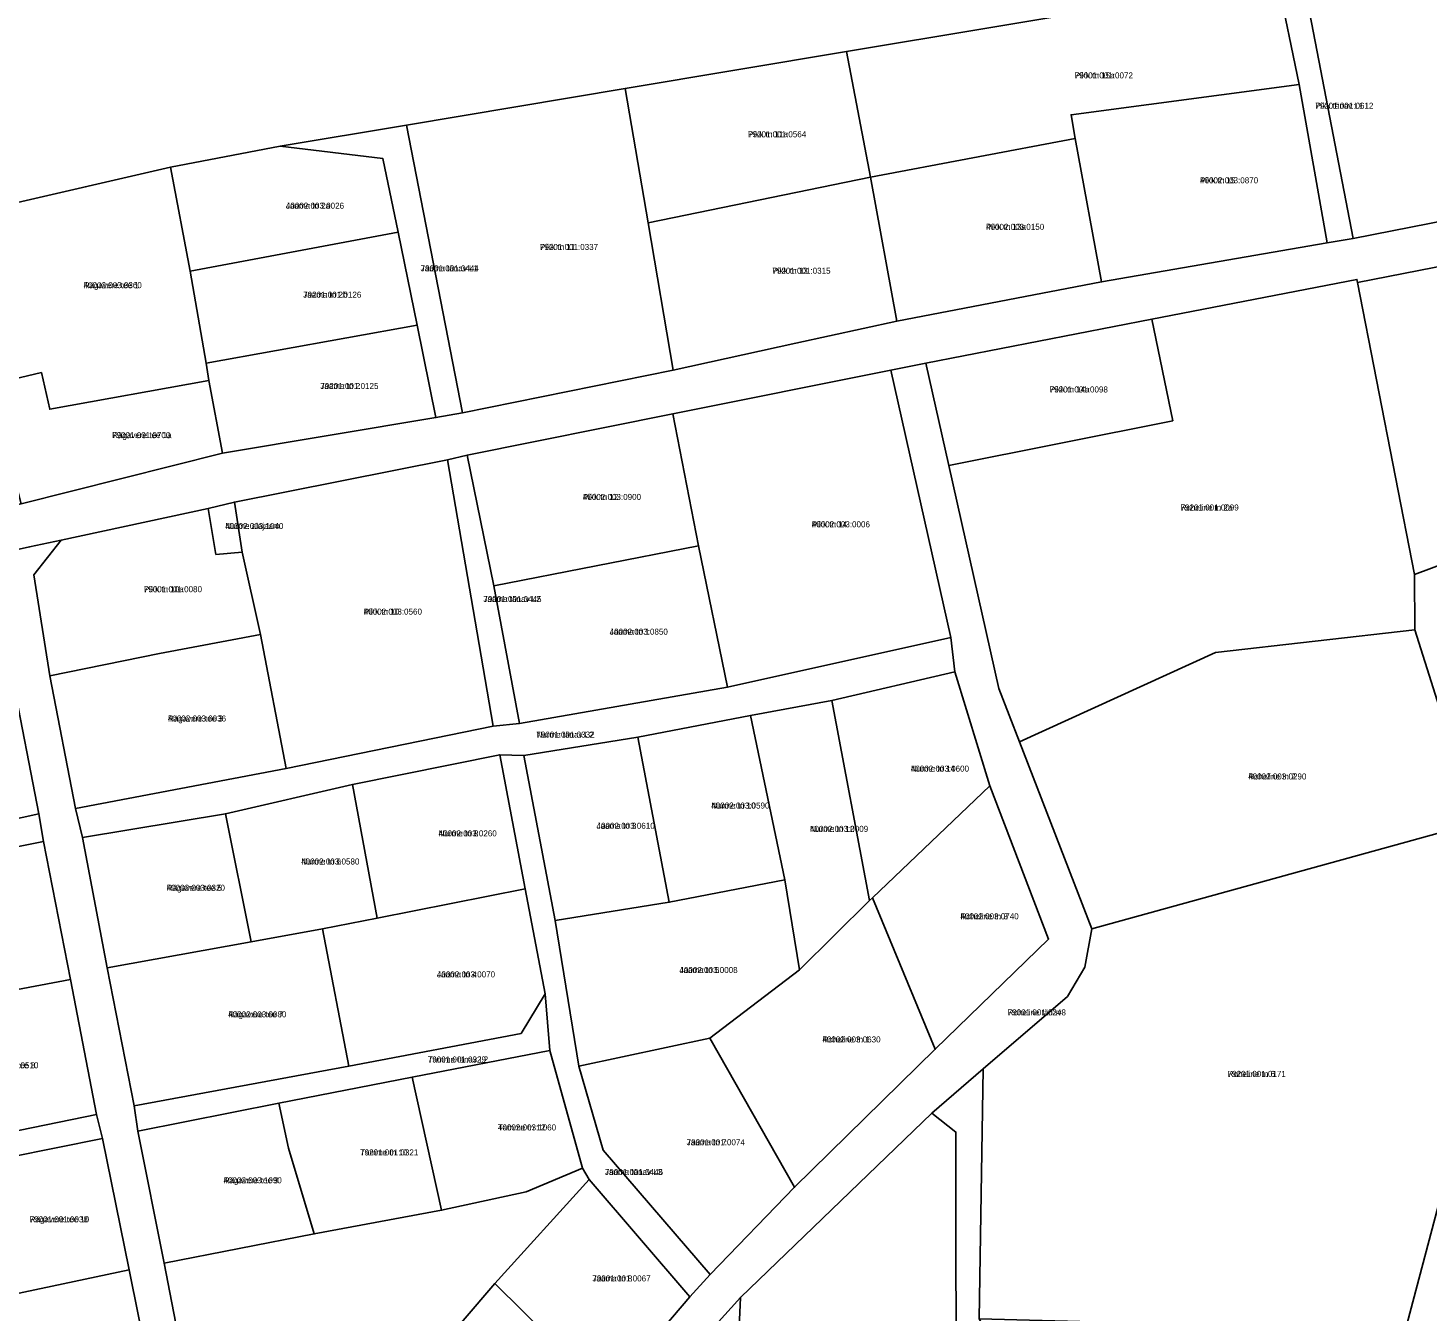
# Model space of a CAD drawing. Extents: x 587616 to 632239, y 6547421 to 6574977.
# Drawn here: x 603991.3 to 604340.3, y 6569543.9 to 6569863.7 of the extents above; entities that cross this region are included whole.
import ezdxf

# ---------------------------------------------------------------- set-up
doc = ezdxf.new("R2010")
doc.units = 0
for name, color, linetype in [('L_AADRESS', 7, 'Continuous'), ('PIIR', 7, 'Continuous'), ('TUNNUS', 7, 'Continuous')]:
    doc.layers.add(name, color=color, linetype=linetype)

msp = doc.modelspace()

# ---------------------------------------------------------------- linework, layer by layer
at = {"layer": 'PIIR'}
for points in [[(604309.05, 6569876.84), (604362.55, 6569882.07), (604367.72, 6569856.07), (604374.56, 6569821.6), (604321.67, 6569811.21)], [(604302.79, 6569875.79), (604308.2, 6569849.61), (604251.38, 6569842.11), (604252.42, 6569836.15), (604201.36, 6569826.5), (604195.4, 6569857.84)], [(604321.67, 6569811.21), (604315.2, 6569810.14), (604308.2, 6569849.61), (604302.79, 6569875.79), (604309.05, 6569876.84)], [(604140.17, 6569848.61), (604195.4, 6569857.84), (604201.36, 6569826.5), (604145.9, 6569815.12)], [(604140.17, 6569848.61), (604145.9, 6569815.12), (604152.2, 6569778.43), (604099.66, 6569767.82), (604085.73, 6569839.51)], [(604308.2, 6569849.61), (604315.2, 6569810.14), (604258.97, 6569800.4), (604252.42, 6569836.15), (604251.38, 6569842.11)], [(604085.73, 6569839.51), (604099.66, 6569767.82), (604093.04, 6569766.6), (604088.36, 6569789.67), (604083.66, 6569812.81), (604079.81, 6569831.16), (604054.24, 6569834.25)], [(604026.9, 6569829.05), (604054.24, 6569834.25), (604079.81, 6569831.16), (604083.66, 6569812.81), (604031.74, 6569803.09)], [(604207.9, 6569790.64), (604201.36, 6569826.5), (604252.42, 6569836.15), (604258.97, 6569800.4)], [(603975.77, 6569811.53), (603984.39, 6569819.23), (604026.9, 6569829.05), (604031.74, 6569803.09), (604035.73, 6569780.14), (604036.42, 6569775.88), (603996.77, 6569768.66), (603994.69, 6569777.81), (603982.09, 6569774.81)], [(604182.74, 6569785.13), (604152.2, 6569778.43), (604145.9, 6569815.12), (604201.36, 6569826.5), (604207.9, 6569790.64)], [(604035.73, 6569780.14), (604031.74, 6569803.09), (604083.66, 6569812.81), (604088.36, 6569789.67)], [(604322.77, 6569800.27), (604376.28, 6569810.72), (604382.05, 6569781.86), (604388.79, 6569746.79), (604337.02, 6569727.45)], [(604276.7, 6569765.81), (604271.48, 6569791.1), (604322.62, 6569801.05), (604322.77, 6569800.27), (604337.02, 6569727.45), (604337.1, 6569713.66), (604287.36, 6569708.03), (604238.55, 6569685.8), (604233.35, 6569699.08), (604220.92, 6569754.62)], [(604036.42, 6569775.88), (604035.73, 6569780.14), (604088.36, 6569789.67), (604093.04, 6569766.6), (604039.82, 6569757.76)], [(604220.92, 6569754.62), (604215.19, 6569780.18), (604271.48, 6569791.1), (604276.7, 6569765.81)], [(604152.07, 6569767.52), (604206.46, 6569778.38), (604221.4, 6569711.75), (604165.69, 6569699.36), (604158.45, 6569734.63)], [(603989.67, 6569745.13), (603982.09, 6569774.81), (603994.69, 6569777.81), (603996.77, 6569768.66), (604036.42, 6569775.88), (604039.82, 6569757.76)], [(604100.86, 6569757.19), (604152.07, 6569767.52), (604158.45, 6569734.63), (604107.44, 6569724.63)], [(604095.88, 6569756.06), (604100.86, 6569757.19), (604107.44, 6569724.63), (604113.84, 6569690.33), (604107.3, 6569689.63)], [(604042.81, 6569745.52), (604095.88, 6569756.06), (604107.3, 6569689.63), (604055.68, 6569679.08), (604049.27, 6569712.49), (604044.72, 6569733.02)], [(604036.28, 6569743.92), (604038.17, 6569732.5), (604044.72, 6569733.02), (604049.27, 6569712.49), (604024.15, 6569707.81), (603996.82, 6569702.19), (603992.82, 6569727.43), (603999.57, 6569736.03)], [(604044.72, 6569733.02), (604038.17, 6569732.5), (604036.28, 6569743.92), (604042.81, 6569745.52)], [(604107.44, 6569724.63), (604158.45, 6569734.63), (604165.69, 6569699.36), (604113.84, 6569690.33)], [(603996.82, 6569702.19), (604024.15, 6569707.81), (604049.27, 6569712.49), (604055.68, 6569679.08), (604003.22, 6569669.18)], [(604004.94, 6569661.89), (604003.22, 6569669.18), (604055.68, 6569679.08), (604107.3, 6569689.63), (604113.84, 6569690.33), (604165.69, 6569699.36), (604221.4, 6569711.75), (604222.38, 6569703.2), (604191.73, 6569696.08), (604171.47, 6569692.35), (604143.36, 6569686.94), (604114.98, 6569682.39), (604108.94, 6569682.55), (604072.21, 6569675.11), (604040.54, 6569667.84)], [(604238.55, 6569685.8), (604287.36, 6569708.03), (604337.1, 6569713.66), (604352.31, 6569665.54), (604256.56, 6569639.11)], [(603987.46, 6569701.73), (603994, 6569667.82), (603942.93, 6569656.57), (603936.63, 6569690.48)], [(604191.73, 6569696.08), (604222.38, 6569703.2), (604231.14, 6569674.78), (604201.87, 6569646.91), (604201.12, 6569646.21)], [(604191.73, 6569696.08), (604201.12, 6569646.21), (604183.66, 6569628.95), (604180.01, 6569651.32), (604171.47, 6569692.35)], [(604143.36, 6569686.94), (604171.47, 6569692.35), (604180.01, 6569651.32), (604151.18, 6569645.77)], [(604114.98, 6569682.39), (604143.36, 6569686.94), (604151.18, 6569645.77), (604122.79, 6569641.23)], [(604115.26, 6569649.15), (604078.36, 6569641.83), (604072.21, 6569675.11), (604108.94, 6569682.55)], [(604108.94, 6569682.55), (604114.98, 6569682.39), (604122.79, 6569641.23), (604128.62, 6569604.94), (604134.71, 6569583.93), (604161.37, 6569552.95), (604156.33, 6569547.41), (604131.26, 6569576.68), (604129.54, 6569579.47), (604121.45, 6569608.8), (604120.25, 6569622.97), (604115.26, 6569649.15)], [(604040.54, 6569667.84), (604072.21, 6569675.11), (604078.36, 6569641.83), (604064.76, 6569639.13), (604046.96, 6569635.91)], [(604201.87, 6569646.91), (604231.14, 6569674.78), (604245.74, 6569636.59), (604217.52, 6569609.13)], [(603778.75, 6569618.82), (603777.58, 6569624.21), (603812.81, 6569630.88), (603832.32, 6569634.77), (603883.98, 6569645.8), (603890.58, 6569647.05), (603942.93, 6569656.57), (603994, 6569667.82), (603995.19, 6569660.95), (603942.95, 6569650.43), (603890.86, 6569640.83), (603885.28, 6569639.59), (603833.25, 6569629.17), (603814.34, 6569625.77)], [(604004.94, 6569661.89), (604040.54, 6569667.84), (604046.96, 6569635.91), (604011.11, 6569629.43)], [(604256.56, 6569639.11), (604352.31, 6569665.54), (604360.92, 6569638.11), (604334.64, 6569538.95), (604319.53, 6569539.5), (604228.48, 6569541.95), (604229.44, 6569604.23), (604250.45, 6569622.25), (604254.82, 6569629.57)], [(603995.19, 6569660.95), (604001.97, 6569626.48), (603950.33, 6569616.81), (603942.95, 6569650.43)], [(604078.36, 6569641.83), (604115.26, 6569649.15), (604120.25, 6569622.97), (604114.24, 6569613.08), (604071.33, 6569604.94), (604064.76, 6569639.13)], [(604180.01, 6569651.32), (604183.66, 6569628.95), (604161.33, 6569611.88), (604128.62, 6569604.94), (604122.79, 6569641.23), (604151.18, 6569645.77)], [(604161.33, 6569611.88), (604183.66, 6569628.95), (604201.12, 6569646.21), (604201.87, 6569646.91), (604217.52, 6569609.13), (604182.45, 6569574.73)], [(604360.92, 6569638.11), (604431.51, 6569646.89), (604362.29, 6569373.98), (604343.36, 6569297.94), (604283.29, 6569296.75), (604283.18, 6569302.74), (604251.37, 6569303.14), (604334.64, 6569538.95)], [(604017.79, 6569595.04), (604011.11, 6569629.43), (604046.96, 6569635.91), (604064.76, 6569639.13), (604071.33, 6569604.94)], [(603950.33, 6569616.81), (604001.97, 6569626.48), (604008.39, 6569592.82), (603956.88, 6569582.28)], [(604018.7, 6569588.68), (604017.79, 6569595.04), (604071.33, 6569604.94), (604114.24, 6569613.08), (604120.25, 6569622.97), (604121.45, 6569608.8), (604087.12, 6569602.19), (604053.88, 6569595.66)], [(604128.62, 6569604.94), (604161.33, 6569611.88), (604182.45, 6569574.73), (604161.37, 6569552.95), (604134.71, 6569583.93)], [(604087.12, 6569602.19), (604121.45, 6569608.8), (604129.54, 6569579.47), (604115.49, 6569573.57), (604094.43, 6569568.97)], [(604216.65, 6569593.17), (604229.44, 6569604.23), (604228.48, 6569541.95), (604234.54, 6569530.24), (604246.61, 6569507.02), (604261.9, 6569495.47), (604225.63, 6569495.88), (604222.76, 6569509.28), (604222.68, 6569588.48)], [(604087.12, 6569602.19), (604094.43, 6569568.97), (604062.72, 6569563.1), (604056.31, 6569584.46), (604053.88, 6569595.66)], [(604018.7, 6569588.68), (604053.88, 6569595.66), (604056.31, 6569584.46), (604062.72, 6569563.1), (604025.25, 6569555.77)], [(604216.65, 6569593.17), (604222.68, 6569588.48), (604222.76, 6569509.28), (604167.31, 6569510.23), (604168.95, 6569547.25)], [(603791.95, 6569545.13), (603790.21, 6569550.5), (603827.74, 6569558.79), (603855.23, 6569562.9), (603898.17, 6569571.42), (603903.85, 6569573.2), (603956.88, 6569582.28), (604008.39, 6569592.82), (604009.88, 6569586.85), (603986.85, 6569582.24), (603966.92, 6569577.74), (603905.52, 6569566.21), (603898.8, 6569565.8), (603847.36, 6569556.19), (603797.71, 6569546.33)], [(603973.78, 6569545.1), (603966.92, 6569577.74), (603986.85, 6569582.24), (604009.88, 6569586.85), (604016.54, 6569554.1)], [(604038.27, 6569488.72), (604025.25, 6569555.77), (604062.72, 6569563.1), (604094.43, 6569568.97), (604115.49, 6569573.57), (604129.54, 6569579.47), (604131.26, 6569576.68), (604107.75, 6569550.7), (604068.73, 6569505.19), (604042.12, 6569490.8)], [(604135.66, 6569523.13), (604107.75, 6569550.7), (604131.26, 6569576.68), (604156.33, 6569547.41)], [(603965.12, 6569543.33), (603973.78, 6569545.1), (604016.54, 6569554.1), (604023.35, 6569520.32), (603971.54, 6569507.11)], [(604042.12, 6569490.8), (604068.73, 6569505.19), (604107.75, 6569550.7), (604135.66, 6569523.13), (604093.34, 6569475.55), (604047.45, 6569465.21)], [(604156.51, 6569533.42), (604168.95, 6569547.25), (604167.31, 6569510.23), (604162.93, 6569482.38), (604153.76, 6569482.49), (604161.23, 6569510.31), (604162.22, 6569528.02), (604161.7, 6569530.08), (604160.55, 6569531.75)]]:
    msp.add_lwpolyline(points, close=True, dxfattribs=at)
for points in [[(604302.79, 6569875.79), (604195.4, 6569857.84), (604140.17, 6569848.61), (604085.73, 6569839.51), (604054.24, 6569834.25), (604026.9, 6569829.05), (603984.39, 6569819.23), (603963.24, 6569815.82), (603913.88, 6569807.86), (603887.81, 6569802.22), (603863.72, 6569797.25), (603855.47, 6569795.6), (603783.15, 6569781.03), (603787.3, 6569756.37), (603786.5, 6569756.22), (603749.29, 6569748.86), (603727.77, 6569861.1), (603752.77, 6569866.34)], [(605043.31, 6569646.26), (604431.51, 6569646.89), (604360.92, 6569638.11), (604352.31, 6569665.54), (604337.1, 6569713.66), (604337.02, 6569727.45), (604388.79, 6569746.79), (604471.41, 6569774.3), (604708.04, 6569853.13), (604838.32, 6569870.09)], [(603173.22, 6569638.29), (603595.83, 6569684.79), (603715.21, 6569698.69), (603715.92, 6569694.81), (603758.63, 6569700.81), (603791.02, 6569706.93), (603817.05, 6569711.73), (603841.21, 6569715.77), (603871.17, 6569721.3), (603878.15, 6569722.45), (603903.43, 6569727.69), (603931.83, 6569733.83), (603977.9, 6569742.85), (603989.67, 6569745.13), (604039.82, 6569757.76), (604093.04, 6569766.6), (604099.66, 6569767.82), (604152.2, 6569778.43), (604182.74, 6569785.13), (604207.9, 6569790.64), (604258.97, 6569800.4), (604315.2, 6569810.14), (604321.67, 6569811.21), (604374.56, 6569821.6)], [(604376.28, 6569810.72), (604322.77, 6569800.27), (604322.62, 6569801.05), (604271.48, 6569791.1), (604215.19, 6569780.18), (604206.46, 6569778.38), (604152.07, 6569767.52), (604100.86, 6569757.19), (604095.88, 6569756.06), (604042.81, 6569745.52), (604036.28, 6569743.92), (603999.57, 6569736.03), (603991.72, 6569734.34), (603982.29, 6569732.31), (603979.07, 6569731.8), (603944.06, 6569726.34), (603878.41, 6569714.5), (603871.17, 6569712.96), (603818.78, 6569701.51), (603764.56, 6569691.72)], [(604135.66, 6569523.13), (604156.33, 6569547.41), (604161.37, 6569552.95), (604182.45, 6569574.73), (604217.52, 6569609.13), (604245.74, 6569636.59), (604231.14, 6569674.78), (604222.38, 6569703.2), (604221.4, 6569711.75), (604206.46, 6569778.38), (604215.19, 6569780.18), (604220.92, 6569754.62), (604233.35, 6569699.08), (604238.55, 6569685.8), (604256.56, 6569639.11), (604254.82, 6569629.57), (604250.45, 6569622.25), (604229.44, 6569604.23), (604216.65, 6569593.17), (604168.95, 6569547.25), (604156.51, 6569533.42)], [(603982.29, 6569732.31), (603991.72, 6569734.34), (603999.57, 6569736.03), (603992.82, 6569727.43), (603996.82, 6569702.19), (604003.22, 6569669.18), (604004.94, 6569661.89), (604011.11, 6569629.43), (604017.79, 6569595.04), (604018.7, 6569588.68), (604025.25, 6569555.77), (604038.27, 6569488.72), (604040.3, 6569474.82), (604042.44, 6569464.1), (604044.26, 6569454.94), (604051.09, 6569420.69), (604054.53, 6569403.44), (604058.03, 6569386.3), (604060.49, 6569374.22), (604073.19, 6569306.11), (604076.71, 6569293.52)], [(604069.43, 6569279.45), (604045.67, 6569401.88), (604031.42, 6569473.35), (604030.48, 6569479.48), (604027.98, 6569494.3), (604024.51, 6569513.82), (604023.35, 6569520.32), (604016.54, 6569554.1), (604009.88, 6569586.85), (604008.39, 6569592.82), (604001.97, 6569626.48), (603995.19, 6569660.95), (603994, 6569667.82), (603987.46, 6569701.73)]]:
    msp.add_lwpolyline(points, dxfattribs=at)

# ---------------------------------------------------------------- texts
at = {"layer": 'L_AADRESS'}
for s, p in [('Pikk tn 15a', (604252.28, 6569851.15)), ('Pikk tänav L1', (604312.23, 6569843.59)), ('Pikk tn 11a', (604170.85, 6569836.48)), ('Pikk tn 15', (604283.51, 6569825)), ('Jaama tn 2a', (604055.63, 6569818.67)), ('Pikk tn 13a', (604230.17, 6569813.4)), ('Pikk tn 11', (604118.96, 6569808.39)), ('Jaama tänav L1', (604089.23, 6569803.06)), ('Pikk tn 13', (604176.91, 6569802.46)), ('Rägavere tee 1', (604005.21, 6569798.86)), ('Jaama tn 2b', (604059.93, 6569796.48)), ('Jaama tn 2', (604064.21, 6569773.72)), ('Pikk tn 14a', (604246.04, 6569772.86)), ('Rägavere tee 1a', (604012.31, 6569761.47)), ('Pikk tn 12', (604129.67, 6569746.07)), ('Roheline tn 2a', (604278.66, 6569743.43)), ('Nurme alajaam', (604040.5, 6569738.82)), ('Pikk tn 14', (604186.73, 6569739.24)), ('Pikk tn 10a', (604020.22, 6569723.06)), ('Pikk tn 10', (604075.05, 6569717.48)), ('Jaama tänav L2', (604104.86, 6569720.61)), ('Jaama tn 1', (604136.35, 6569712.48)), ('Rägavere tee 3', (604026.22, 6569690.83)), ('Nurme tänav L2', (604118.08, 6569686.82)), ('Nurme tn 14', (604211.43, 6569678.34)), ('Roheline tn 2', (604295.53, 6569676.38)), ('Nurme tn 10', (604161.68, 6569669.13)), ('Nurme tn 8', (604093.7, 6569662.19)), ('Jaama tn 3', (604133.08, 6569664.08)), ('Nurme tn 12', (604186.29, 6569663.32)), ('Nurme tn 6', (604059.45, 6569655.18)), ('Rägavere tee 5', (604025.93, 6569648.63)), ('Roheline tn 3', (604223.8, 6569641.52)), ('Jaama tn 4', (604093.28, 6569627.04)), ('Jaama tn 5', (604153.74, 6569628.13)), ('Rägavere tee 7', (604041.25, 6569617.08)), ('Roheline tänav', (604235.58, 6569617.56)), ('Roheline tn 1', (604189.38, 6569610.82)), ('Tamme tänav L2', (604091, 6569605.82)), ('Rägavere tee 8', (603979.44, 6569604.38)), ('Roheline tn 6', (604290.41, 6569602.24)), ('Tamme tn 12', (604108.5, 6569588.88)), ('Jaama tn 7', (604155.54, 6569585.19)), ('Tamme tn 10', (604074.14, 6569582.65)), ('Jaama tänav L3', (604135.15, 6569577.77)), ('Rägavere tee 9', (604040.11, 6569575.71)), ('Rägavere tee 10', (603991.76, 6569565.98)), ('Jaama tn 8', (604132.04, 6569551.24))]:
    msp.add_text(s, height=1.5, dxfattribs=at).set_placement(p)
at = {"layer": 'TUNNUS'}
for s, p in [('79001:001:0072', (604252.28, 6569851.15)), ('79201:001:0612', (604312.23, 6569843.59)), ('79201:001:0564', (604170.85, 6569836.48)), ('40002:003:0870', (604283.51, 6569825)), ('40002:003:0026', (604055.63, 6569818.67)), ('40002:003:0150', (604230.17, 6569813.4)), ('79201:001:0337', (604118.96, 6569808.39)), ('79001:001:0444', (604089.23, 6569803.06)), ('79201:001:0315', (604176.91, 6569802.46)), ('40002:003:0360', (604005.21, 6569798.86)), ('79201:001:0126', (604059.93, 6569796.48)), ('79201:001:0125', (604064.21, 6569773.72)), ('79201:001:0098', (604246.04, 6569772.86)), ('79001:001:0700', (604012.31, 6569761.47)), ('40002:003:0900', (604129.67, 6569746.07)), ('79201:001:0099', (604278.66, 6569743.43)), ('40002:003:1040', (604040.5, 6569738.82)), ('40002:003:0006', (604186.73, 6569739.24)), ('79001:001:0080', (604020.22, 6569723.06)), ('40002:003:0560', (604075.05, 6569717.48)), ('79001:001:0445', (604104.86, 6569720.61)), ('40002:003:0850', (604136.35, 6569712.48)), ('40002:003:0036', (604026.22, 6569690.83)), ('79001:001:0332', (604118.08, 6569686.82)), ('40002:003:0600', (604211.43, 6569678.34)), ('40002:003:0290', (604295.53, 6569676.38)), ('40002:003:0590', (604161.68, 6569669.13)), ('40002:003:0260', (604093.7, 6569662.19)), ('40002:003:0610', (604133.08, 6569664.08)), ('40002:003:0009', (604186.29, 6569663.32)), ('40002:003:0580', (604059.45, 6569655.18)), ('40002:003:0320', (604025.93, 6569648.63)), ('40002:003:0740', (604223.8, 6569641.52)), ('40002:003:0070', (604093.28, 6569627.04)), ('40002:003:0008', (604153.74, 6569628.13)), ('40002:003:0080', (604041.25, 6569617.08)), ('79001:001:0248', (604235.58, 6569617.56)), ('40002:003:0630', (604189.38, 6569610.82)), ('79001:001:0329', (604091, 6569605.82)), ('40002:003:0510', (603979.44, 6569604.38)), ('79201:001:0171', (604290.41, 6569602.24)), ('40002:003:1060', (604108.5, 6569588.88)), ('79001:001:0074', (604155.54, 6569585.19)), ('79201:001:0321', (604074.14, 6569582.65)), ('79001:001:0446', (604135.15, 6569577.77)), ('40002:003:1090', (604040.11, 6569575.71)), ('79001:001:0038', (603991.76, 6569565.98)), ('79001:001:0067', (604132.04, 6569551.24))]:
    msp.add_text(s, height=1.5, dxfattribs=at).set_placement(p)

doc.saveas('drawing.dxf')
